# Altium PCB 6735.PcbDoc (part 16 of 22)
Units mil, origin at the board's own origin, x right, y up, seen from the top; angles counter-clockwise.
Board outline 2641.73 x 5165.35 mil, 6 copper layers (Top, Inner Layer 2, Inner Layer 3, Inner Layer 4, Inner Layer 5, Bottom), stack 35.7 mil thick; 1011 components, 790 nets, 4118 pads, 9325 vias.
Unrouted connection lines stored in the file: 4610.
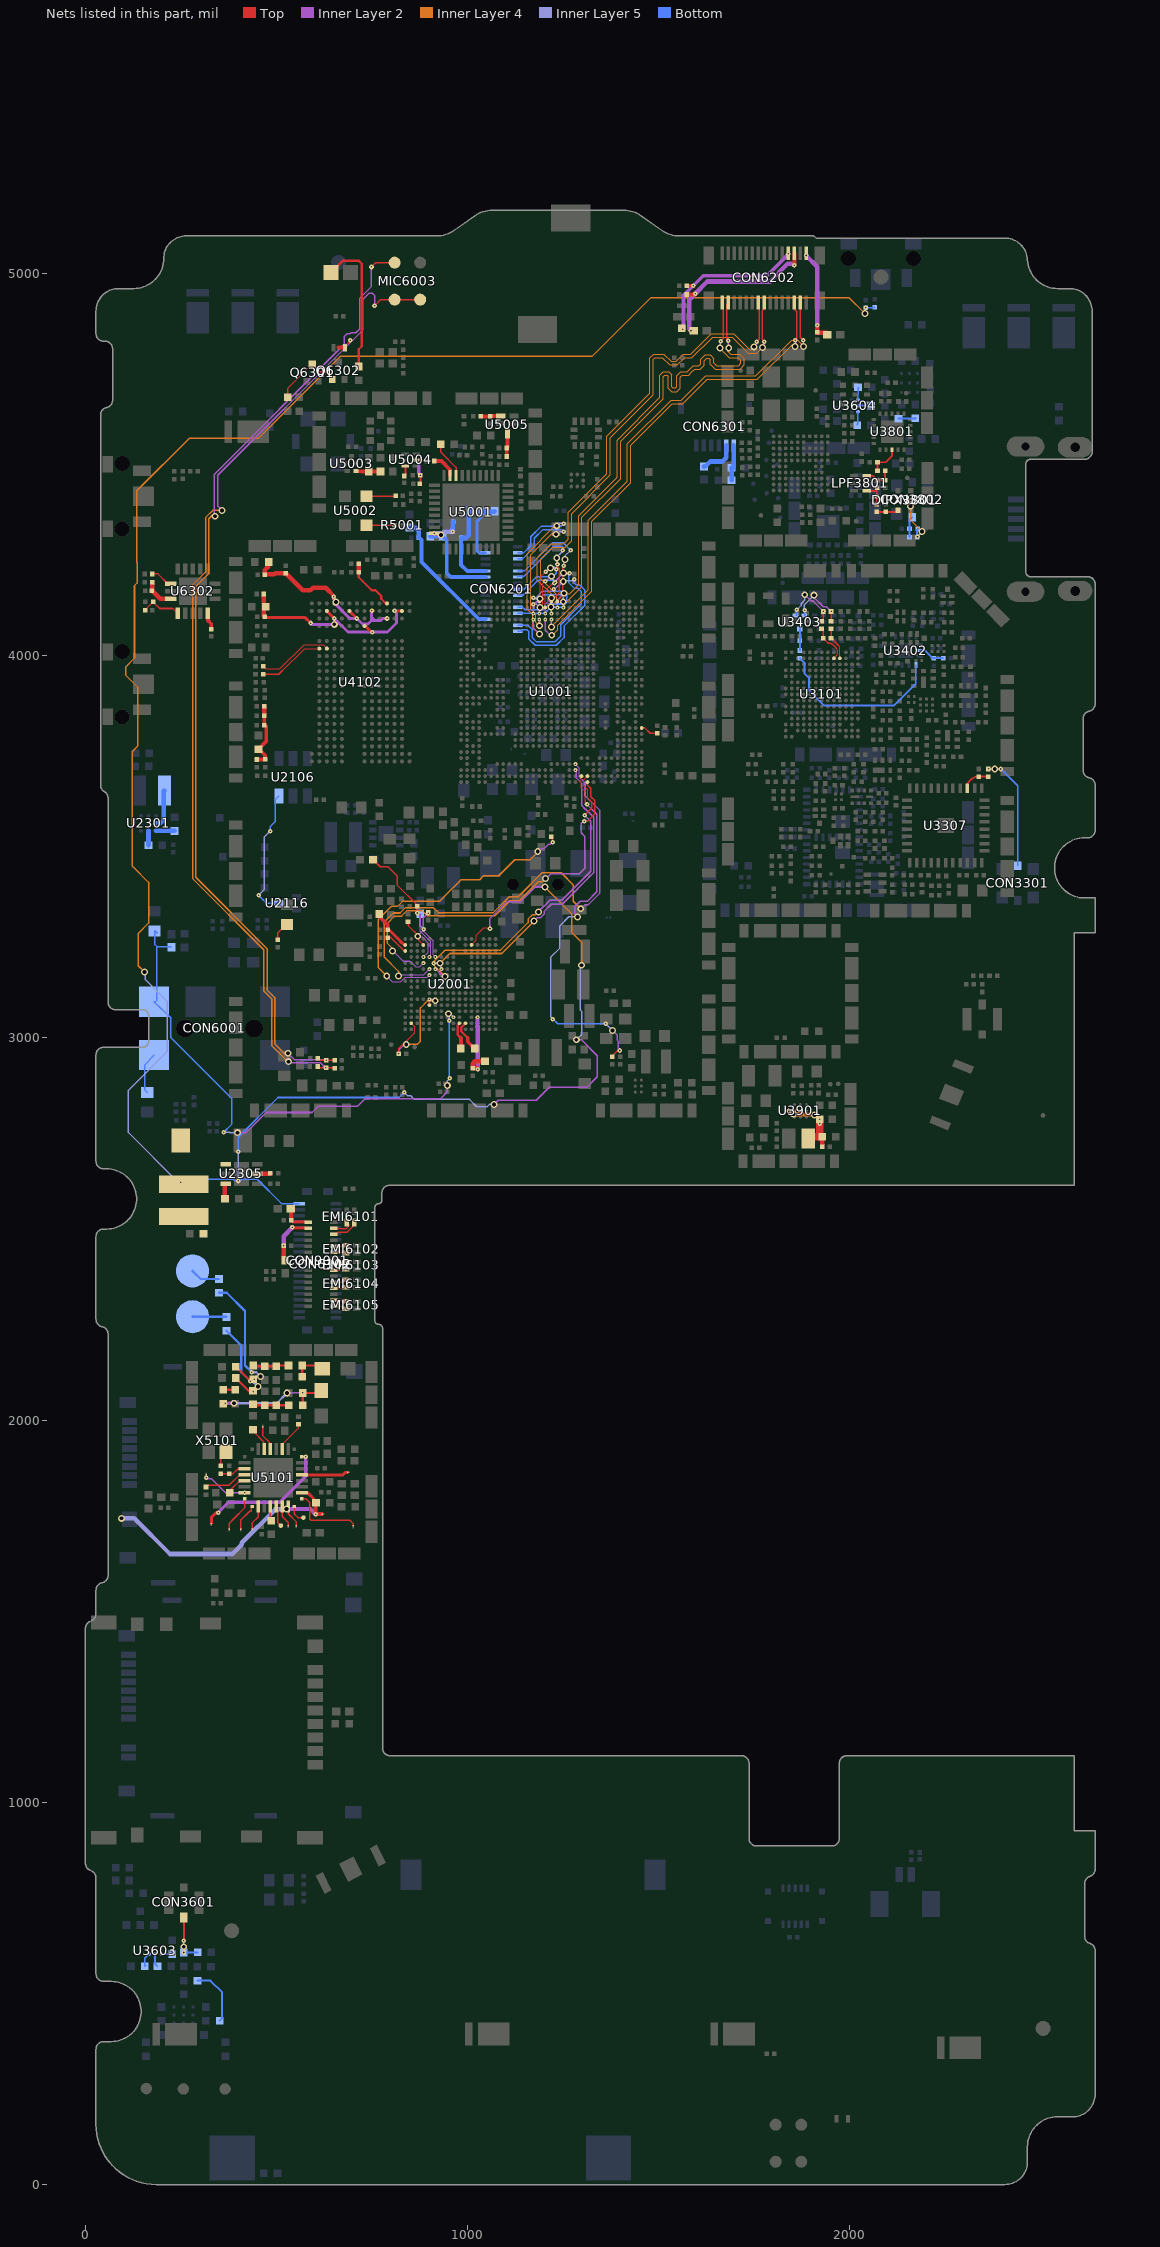
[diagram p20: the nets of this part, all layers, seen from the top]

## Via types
v1: diameter 12, hole 4, Top to Inner Layer 2, 3329 vias
v2: diameter 12, hole 4, Inner Layer 5 to Bottom, 3071 vias
v3: diameter 18, hole 10, Inner Layer 2 to Inner Layer 5, 1928 vias
v4: diameter 10, hole 4, Top to Inner Layer 2, 525 vias
v5: diameter 20, hole 12, Top to Bottom, 472 vias

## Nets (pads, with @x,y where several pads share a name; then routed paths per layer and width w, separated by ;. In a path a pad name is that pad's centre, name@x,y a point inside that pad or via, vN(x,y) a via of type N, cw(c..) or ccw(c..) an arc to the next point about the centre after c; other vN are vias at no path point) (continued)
N21349567: D6301.1 R6350.2 | length 367.8
  Top w6: D6301.1@642.78,5002.92 672.82,5032.96 715.61,5032.96 722.95,5025.62 722.95,4809.85 714.88,4801.77 R6350.2@714.88,4756.78
N21349614: Q6301.3 Q6302.1 R6352.2 | length 183.6
  Top w4: R6352.2@528.95,4675.99 528.95,4699.11 592.97,4763.13 Q6301.3@593.95,4763.13 594.94,4763.13 615.07,4742.99 626.55,4742.99 645.7,4723.84 Q6302.1@645.7,4722.85
N22234659: C6203.1 CON6201.29 R6201.1 | length 169.8
  Bottom w8: C6203.1@1038.72,4377.31 1034.95,4377.31 1034.95,4361.49 1023.95,4350.49 1023.95,4274.77 1029.83,4268.89 CON6201.29@1046.63,4268.89
  Bottom w12: C6203.1@1038.72,4377.31 1038.72,4377.09 1071.31,4377.09 R6201.1@1071.31,4378.09
N22234883: C6202.1 CON6201.18 R6204.1 | length 341.9
  Bottom w10: C6202.1@872.31,4309.09 878.95,4302.45 878.95,4245.54 1028.83,4095.66 CON6201.18@1046.63,4095.66
  Bottom w12: R6204.1@847.95,4335.49 847.95,4334.49 863.95,4334.49 872.31,4326.12 C6202.1@872.31,4309.09
N22234972: C6210.1 CON6202.6 R6209.1 | length 462.4
  Top w4: v1(1584.3,4850.09) R6209.1@1591.31,4850.09
  Top w10: C6210.1@1573.31,4945.09 1573.31,4945.42 1595.31,4945.42 v1(1595.31,4947.09) ; v1(1854.31,5022.09) 1854.69,5022.09 CON6202.6@1854.69,5053.06
  Inner Layer 2 w12: v1(1584.3,4850.09) 1579.31,4855.08 1579.31,4931.09 v1(1595.31,4947.09) 1627.31,4979.09 1790.92,4979.09 1836.92,5025.09 1854.31,5025.09 v1(1854.31,5022.09)
N22234982: C6207.1 CON6202.8 R6207.1 | length 431.4
  Top w4: R6207.1@1560.31,4857.09 v1(1563.31,4854.09)
  Top w8: C6207.1@1573.31,4968.09 1573.31,4968.16 1587.24,4968.16 1588.81,4966.59 v1(1590.31,4968.09)
  Inner Layer 2 w10: v1(1563.31,4854.09) 1564.31,4855.09 1564.31,4942.09 v1(1590.31,4968.09) 1616.31,4994.09 1783.06,4994.09 1830.78,5041.81 1830.78,5042.9 v1(1838.94,5051.05)
N22234984: C6206.1 CON6202.2 R6205.1 | length 246
  Top w12: v1(1914.31,4865.09) C6206.1@1914.31,4846.09 1914.31,4845.09 1940.31,4845.09 1940.31,4840.09 R6205.1@1941.31,4840.09
  Inner Layer 2 w12: v1(1885.31,5047.09) 1914.31,5018.09 v1(1914.31,4865.09)
N22235094: C6204.2 CON6201.25 R6203.1 | length 239.2
  Bottom w10: C6204.2@934.95,4311.99 945.31,4301.62 945.31,4216.12 955.54,4205.9 CON6201.25@1046.63,4205.9
  Bottom w12: R6203.1@902.45,4312.99 902.45,4311.99 C6204.2@934.95,4311.99
N22235098: C6201.1 CON6201.26 R6202.1 | length 230.3
  Bottom w10: C6201.1@982.95,4307.99 982.95,4237.49 998.79,4221.64 CON6201.26@1046.63,4221.64
  Bottom w12: C6201.1@982.95,4307.99 994.95,4307.99 1002.45,4315.49 1002.45,4374.99 R6202.1@1006.45,4378.99 ; R6202.1@1006.45,4379.99 R6202.1@1006.45,4378.99 ; R6202.1@1007.24,4378.99 R6202.1@1006.45,4378.99
N22266286: CON6102.28 EMI6101.3 | length 71.7
  Top w4: CON6102.28@649.55,2486.73 651.91,2489.09 658.31,2489.09 661.31,2492.09 684.78,2492.09 704.81,2512.12 704.81,2517.07 EMI6101.3@703.8,2517.07
N22266288: CON6102.29 EMI6101.2 | length 54.4
  Top w4: CON6102.29@649.55,2502.48 651.94,2500.09 681.31,2500.09 688.31,2507.09 688.31,2512.86 EMI6101.2@684.11,2517.07
N22266347: CON6102.22 EMI6103.3 | length 33.6
  Top w4: CON6102.22@649.55,2392.24 662.45,2392.24 665.81,2395.59 667.31,2397.09 676.62,2397.09 678.09,2395.62 EMI6103.3@680.54,2395.25
N22266349: CON6102.23 EMI6103.2 | length 38.1
  Top w4: CON6102.23@649.55,2407.99 665.63,2407.99 675.59,2417.94 680.54,2417.94 EMI6103.2@680.54,2414.93
N22266395: CON6102.19 EMI6104.3 | length 33.3
  Top w4: CON6102.19@649.55,2345 680.54,2344.99 EMI6104.3@680.54,2347.25
N22266397: CON6102.20 EMI6104.2 | length 33.6
  Top w4: CON6102.20@649.55,2360.75 674.35,2360.74 EMI6104.2@680.54,2366.93
N22266410: CON6102.25 EMI6102.3 | length 31.9
  Top w4: CON6102.25@649.55,2439.49 678.3,2439.48 EMI6102.3@680.54,2437.25
N22266412: CON6102.26 EMI6102.2 | length 31.7
  Top w4: CON6102.26@649.55,2455.23 678.84,2455.23 EMI6102.2@680.54,2456.93
N22266425: CON6102.16 EMI6105.3 | length 37.9
  Top w4: CON6102.16@649.55,2297.75 671.03,2297.75 680.54,2288.25 EMI6105.3@680.54,2291.25
N22266427: CON6102.17 EMI6105.2 | length 36.3
  Top w4: CON6102.17@649.55,2313.5 674.97,2313.5 679.04,2309.43 680.54,2307.93 EMI6105.2@680.54,2310.93
N33629520: C4111.1 C4112.1 R4101.1 U4102.B3 U4102.B12 U4102.B13 U4102.C4 U4102.D8 | length 571.9
  Top w4: C4111.1@466.95,4132.82 471.31,4132.82 C4111.1@471.31,4128.09
  Top w8: C4112.1@468.95,4101.49 470.95,4099.49 574.95,4099.49 v1(588.95,4085.49) ; U4102.B3@631.5,4117.12 v1(651.18,4097.43) ; U4102.D8@729.93,4077.75 730.98,4078.8 748.98,4060.8 v1(750.03,4061.85) ; v1(808.66,4117.11) U4102.B13@828.35,4117.12
  Top w12: C4111.1@466.95,4132.82 466.95,4103.49 C4112.1@468.95,4101.49 ; C4111.1@466.95,4133.49 R4101.1@466.95,4161.49
  Inner Layer 2 w8: v1(588.95,4085.49) 592.33,4082.11 v3(651.08,4082.11) 651.08,4097.33 v1(651.18,4097.43) 686.76,4061.85 v1(750.03,4061.85) 790.32,4061.85 813.95,4085.49 813.95,4111.83 v1(808.66,4117.11)
N33629528: C4113.1 C4114.1 R4102.1 U4102.A4 U4102.B6 U4102.B9 U4102.C7 U4102.C11 | length 521.7
  Top w8: v1(649.08,4154.11) 651.18,4152.11 U4102.A4@651.19,4136.8 ; U4102.B6@690.56,4117.12 v1(710.24,4097.43)
  Top w10: 638.95,4167.44 650.68,4155.71 v1(649.08,4154.11)
  Top w12: R4102.1@469.31,4212.09 R4102.1@469.31,4213.25 ; C4113.1@479.31,4245.09 478.31,4245.09 478.31,4233.11 469.31,4224.11 R4102.1@469.31,4213.25 ; 638.95,4167.44 628.9,4177.49 615.9,4177.49 615.56,4177.83 595.62,4177.83 588.62,4170.83 568.61,4170.83 C4114.1@523.95,4215.49 496.63,4215.49 494.39,4213.25 R4102.1@469.31,4213.25
  Inner Layer 2 w8: v1(649.08,4154.11) 649.08,4147.11 655.08,4141.11 v3(655.08,4140.11) 655.08,4135.11 654.58,4134.61 691.76,4097.43 v1(710.24,4097.43) 724.95,4082.72 739.17,4082.72 748.3,4091.85 748.3,4092.18 ; v1(749.61,4117.11) 748.3,4115.81 748.3,4101.24 ; v1(788.98,4097.43) 788.08,4097.64 778.73,4097.64 773.27,4092.18 757.37,4092.18 ; 748.3,4092.18 757.37,4092.18 ; 748.3,4092.18 748.3,4101.24 ; 748.3,4101.24 757.37,4092.18
N33630206: C4109.1 C4110.1 U4102.A11 | length 143.1
  Top w4: U4102.A11@788.98,4136.8 788.98,4137.46 U4102.A11@788.98,4136.8
  Top w6: C4110.1@714.95,4218.49 714.95,4205.45 749.31,4171.09 758.86,4171.09 773.8,4156.15 773.8,4148.91 785.9,4136.8 U4102.A11@788.98,4136.8
  Top w12: C4110.1@714.95,4218.49 C4109.1@714.95,4240.49
N33630402: R4103.2 U4102.G2 | length 174.7
  Top w3: 514.95,3960.49 573.15,4018.69 U4102.G2@611.82,4018.69
  Top w4: R4103.2@464.95,3951.49 505.95,3951.49 514.95,3960.49
N33630406: R4104.2 U4102.G3 | length 199.7
  Top w3: R4104.2@464.95,3972.49 471.95,3965.49 508.95,3965.49 572.02,4028.56 621.63,4028.56 U4102.G3@631.5,4018.69
N35189465: L5002.2 U5001.38 | length 98.7
  Top w4: L5002.2@929.31,4553.09 929.31,4532.8 969.71,4492.4 U5001.38@969.71,4471.17
N35189467: R5015.1 U5004.6 | length 27.6
  Top w4: R5015.1@834.08,4470.11 834.08,4471.11 837.3,4474.33 U5004.6@837.3,4496.36
N35189484: L5007.1 R5014.2 U5005.4 | length 53.3
  Top w10: R5014.2@1034.31,4626.09 L5007.1@1059.08,4626.11 1059.08,4626.8 U5005.4@1086.86,4626.8
N35189556: C5013.1 C5014.1 U5001.9 | length 90.4
  Inner Layer 2 w12: v1(913.02,4319.99) 913.02,4319.09 930.31,4319.09 v3(930.31,4316.09)
  Inner Layer 5 w12: v3(930.31,4316.09) 930.24,4316.16 938.06,4323.99 v2(961.43,4323.99)
  Bottom w4: v2(961.43,4323.99) 961.42,4327.97 959.45,4330.99 961.45,4328.99 961.95,4328.49 C5013.1@961.45,4328.49
  Bottom w12: C5013.1@961.45,4327.99 961.45,4328.49 961.45,4328.99 961.45,4350.49 C5014.1@961.95,4350.49
N35189587: R5007.2 U5001.39 | length 66
  Top w10: R5007.2@912.95,4509.49 931.13,4509.49 953.96,4486.66 U5001.39@953.96,4471.17
N35190528: R5003.1 U5002.4 | length 77.1
  Top w4: U5002.4@735.43,4417.1 786.02,4417.1 ; 786.03,4417.11 809.57,4417.11 810.95,4418.49 R5003.1@811.95,4418.49
N35190536: R5001.1 U5002.3 | length 73.7
  Top w4: U5002.3@735.43,4341.12 791.13,4341.11 R5001.1@809.08,4341.11
N35190564: C5012.2 R5008.1 U5004.2 | length 67.6
  Top w5: U5004.2@864.86,4512.11 865.08,4511.89 v1(865.08,4511.11) ; R5008.1@875.08,4450.11 876.08,4450.11 v1(876.08,4472.11)
  Inner Layer 2 w8: v1(865.08,4511.11) 871.95,4504.24 871.95,4476.24 v1(876.08,4472.11)
N35190588: C5011.1 L5003.1 U5003.4 | length 64.9
  Top w10: U5003.4@707.4,4482.74 722.3,4482.74 722.93,4482.11 C5011.1@741.08,4482.11 L5003.1@772.08,4482.11
N35190689: C5016.1 L5006.1 U5005.1 | length 60.6
  Top w10: C5016.1@1102.08,4521.11 1102.08,4543.49 L5006.1@1101.95,4543.49 1104.08,4545.62 U5005.1@1104.08,4580.69
N42705003: C5102.1 R5102.2 R5104.1 | length 368.7
  Top w4: R5104.1@439.31,2107.09 440.31,2106.09 v1(441.31,2107.09)
  Top w6: C5102.1@393.31,2140.09 426.31,2107.09 R5104.1@439.31,2107.09 v1(441.31,2107.09)
  Inner Layer 2 w4: v1(441.31,2107.09) 440.43,2107.97 446.95,2114.49 v3(457.95,2114.49)
  Inner Layer 5 w6: v2(434.95,2125.49) 446.95,2125.49 v3(457.95,2114.49)
  Bottom w6: R5102.2@349.31,2333.09 369.95,2333.09 417.31,2285.72 417.31,2143.12 v2(434.95,2125.49)
N42705119: C5117.2 U5101.22 | length 64.3
  Top w4: C5117.2@438.31,1975.09 438.31,1971.31 465.95,1943.67 465.95,1923.99 U5101.22@467.68,1923.99
N42705839: C5110.1 R5105.2 | length 32
  Top w6: C5110.1@360.31,2079.09 R5105.2@392.31,2079.09
N42705853: C5105.2 C5107.2 C5109.1 R5104.2 | length 96
  Top w6: R5104.2@439.31,2143.09 439.31,2141.09 C5105.2@469.31,2141.09 C5107.2@499.31,2141.09 499.31,2143.09 C5109.1@531.31,2143.09
N42705857: C5108.2 C5110.2 C5111.1 L5101.2 | length 319.4
  Top w4: C5110.2@359.32,2043.09 C5110.2@360.31,2043.09 ; C5110.2@359.31,2044.09 C5110.2@360.31,2043.09 ; v1(365.31,2044.09) 361.31,2044.09 C5110.2@360.31,2043.09
  Top w6: C5108.2@568.1,2039.09 C5108.2@568.31,2039.09 v1(568.31,2071.09) ; C5111.1@569.31,2072.09 v1(568.31,2071.09) ; L5101.2@608.81,2086.09 L5101.2@617.31,2077.59 610.81,2071.09 v1(568.31,2071.09)
  Inner Layer 2 w4: v3(527.31,2071.09) v1(568.31,2071.09)
  Inner Layer 2 w9: v1(365.31,2044.09) 384.31,2044.09 v3(388.82,2044.08)
  Inner Layer 5 w6: v3(388.82,2044.08) 500.31,2044.09 v3(527.31,2071.09)
N42705859: R5108.1 R5130.2 U5101.27 | length 67.3
  Top w4: R5108.1@354.31,1860.09 R5130.2@376.31,1860.09 386.13,1860.09 398.75,1872.71 U5101.27@416.4,1872.71
N42705927: C5104.1 C5106.1 C5108.1 R5103.2 | length 96
  Top w6: R5103.2@438.31,2041.09 438.31,2039.09 C5106.1@469.31,2039.09 C5104.1@499.31,2039.09 C5108.1@532.31,2039.09
N42705929: R5116.2 U5101.4 | length 40
  Top w4: U5101.4@483.43,1774.19 483.43,1737.09 R5116.2@486.3,1737.09
N42705933: C5101.1 R5101.2 R5103.1 | length 269.1
  Top w4: R5103.1@438.31,2077.09 439.31,2077.09 v1(439.31,2074.09)
  Top w6: C5101.1@393.31,2110.09 428.31,2075.09 438.31,2075.09 R5103.1@438.31,2077.09
  Inner Layer 2 w4: v1(439.31,2074.09) 438.92,2074.48 451.86,2087.43 v3(451.46,2087.83)
  Inner Layer 5 w6: v2(430.95,2101.49) 437.31,2101.49 440.68,2098.09 441.2,2098.09 v3(451.46,2087.83)
  Bottom w6: R5101.2@368.95,2233.83 407.31,2195.47 407.31,2125.12 v2(430.95,2101.49)
N42705947: C5109.2 C5112.2 L5102.2 | length 87.8
  Top w6: C5112.2@567.31,2113.09 C5109.2@567.31,2143.09 613.52,2143.09 619.81,2136.8 L5102.2@619.81,2134.09
N42705966: C5116.2 U5101.19 | length 83.7
  Top w4: U5101.19@514.92,1923.99 514.21,1923.99 514.21,1936.02 557.31,1979.13 C5116.2@557.31,1989.09
N42706036: C5119.2 U5101.29 | length 57.4
  Top w4: C5119.2@377.31,1810.09 377.31,1810.67 376.73,1810.67 381.31,1815.26 381.31,1819.49 404.06,1842.23 416.4,1842.23 U5101.29@416.4,1841.22
N42706071: C5120.2 U5101.28 | length 115.5
  Top w4: C5120.2@315.31,1825.09 320.31,1830.09 376.46,1830.09 404.21,1857.83 416.4,1857.83 U5101.28@416.4,1856.96
N42706085: R5108.2 X5101.1 | length 43.1
  Top w4: R5108.2@354.31,1880.09 354.31,1903.91 X5101.1@367.95,1917.55
N42706217: ANT5101.1 R5101.1 | length 90.9
  Bottom w6: ANT5101.1@281.08,2271.49 ANT5101.1@280.08,2270.49 368.95,2270.49 R5101.1@368.95,2269.83
N42706219: ANT5102.1 R5102.1 | length 78.1
  Bottom w6: ANT5102.1@280.08,2390.49 301.48,2369.09 R5102.1@349.31,2369.09
N42706237: TP5101.1 U5101.8 | length 47.5
  Top w4: U5101.8@546.42,1774.19 546.42,1754.42 555.75,1745.09 TP5101.1@570.31,1745.09
N42706293: TP5102.1 U5101.5 | length 55.1
  Top w4: U5101.5@499.18,1774.19 502.95,1770.41 502.95,1732.44 TP5102.1@511.3,1724.09
N45548966: C6034.2 C6035.1 MIC6003.4 R6025.1 | length 2598.1
  Top w4: C6035.1@607.68,2946.69 612.28,2942.09 C6034.2@630.31,2942.09 ; v1(630.31,2941.09) C6034.2@630.31,2942.09 ; R6025.1@652.31,2942.09 C6034.2@630.31,2942.09 ; v1(748.31,5017.09) 759.74,5028.52 MIC6003.4@808.85,5028.52
  Inner Layer 2 w4: v3(338.95,4364.83) 336.94,4366.84 336.94,4474.3 677.31,4814.67 677.31,4835.09 684.31,4842.09 692.31,4842.09 694.89,4844.67 707.31,4844.67 717.95,4855.31 717.95,4935.72 748.31,4966.09 v1(748.31,5017.09) ; v3(529.95,2959.83) 530.17,2960.05 547.13,2943.09 628.31,2943.09 v1(630.31,2941.09)
  Inner Layer 4 w4: v3(338.95,4364.83) 334.69,4369.09 333.31,4369.09 322.31,4358.09 322.31,4215.25 288.31,4181.25 288.31,3420.17 475.31,3233.17 475.31,3125.41 495.31,3105.41 495.31,2984.03 519.51,2959.83 v3(529.95,2959.83)
N45548968: C6034.1 C6039.1 MIC6003.2 MIC6003.3 R6026.1 SH6004.1 | length 2702
  Top w4: C6039.1@607.31,2925.09 610.31,2925.09 613.31,2922.09 v1(628.31,2922.09) C6034.1@630.31,2922.09 642.31,2922.09 ; R6026.1@652.31,2921.09 R6026.1@651.31,2921.09 ; SH6004.1@679.31,4806.09 679.31,4810.09 693.31,4824.09 695.31,4824.09 v1(693.18,4825.73) ; v1(756.3,4915.09) 772.88,4931.66 MIC6003.3@808.85,4931.66 MIC6003.2@875.78,4931.66 ; 642.31,2922.09 650.31,2922.09 R6026.1@651.31,2921.09 ; 642.31,2922.09 643.31,2921.09 R6026.1@651.31,2921.09
  Inner Layer 2 w4: v3(357.31,4380.09) 345.87,4391.53 345.87,4471.9 693.18,4819.21 ; v3(530.95,2937.83) 530.95,2936.09 535.31,2936.09 536.31,2935.09 614.63,2935.09 627.63,2922.09 v1(628.31,2922.09) ; v1(756.3,4915.09) 756.3,4942.48 750.42,4948.36 741.9,4948.36 725.95,4932.41 725.95,4851.98 v1@697.06,4823.09 ; 693.18,4819.21 v1(693.18,4825.73) 695.31,4824.09 695.69,4824.47 v1@697.06,4823.09 ; 693.18,4819.21 v1@697.06,4823.09
  Inner Layer 4 w4: v3(357.31,4380.09) 333,4380.09 314.31,4361.4 314.31,4218.91 280.31,4184.91 280.31,3416.77 466.31,3230.77 466.31,3123.09 487.31,3102.09 487.31,2980.43 530.43,2937.31 v3(530.95,2937.83)
N46126307: C1101.2 C1102.1 C1103.1 R1103.2 R1105.2 R1106.1 | length 183
  Top w3: C1102.1@467.81,3818.33 C1102.1@467.81,3820.33 ; R1106.1@467.81,3837.33 R1106.1@467.81,3843.33
  Top w10: C1101.2@447.81,3728.33 447.81,3728.54 R1105.2@470.13,3728.54 470.13,3739.54 C1103.1@453.57,3756.09 ; R1106.1@467.81,3837.33 467.81,3820.33 472.81,3815.33 472.81,3775.33 C1103.1@453.57,3756.09 ; C1103.1@453.57,3756.09 453.57,3755.33 C1103.1@452.81,3755.33 C1103.1@453.57,3756.09
  Top w12: R1106.1@467.81,3843.33 467.81,3855.35 467.95,3855.49 R1103.2@467.95,3867.49
N46488991: R2003.2 U2001.N2 | length 76.9
  Top w4: R2003.2@843.95,3303.49 843.95,3294.41 872.31,3266.04 872.31,3254.96 U2001.N2@884.09,3243.19
N46497626: C2008.1 R2026.2 | length 51
  Top w4: R2026.2@503.31,3257.09 503.31,3274.66 525.56,3296.91 C2008.1@527.56,3296.91
N46513471: C2038.1 U2001.G15 | length 75.8
  Top w4: C2038.1@982.31,2972.15 C2038.1@986.31,2972.15
  Top w6: U2001.G15@978.57,3038.47 973.85,3033.74 973.85,3008.55 979.25,3003.15
  Top w10: 979.25,3003.15 982.31,3000.09 C2038.1@982.31,2972.15
N46513473: C2038.2 U2001.F15 | length 85.6
  Top w6: U2001.F15@994.32,3038.47 983.26,3027.41 983.26,3016.81 990.31,3009.76 990.64,3009.76 1000.31,3000.09
  Top w10: 1000.31,3000.09 1000.31,2990.15 C2038.2@1018.31,2972.15
N46513502: C2022.1 R2048.1 U2001.D14 | length 209.5
  Top w4: v1(1026.48,2918.32) 1029.31,2918.09 1030.31,2919.09 v1(1026.48,2918.32)
  Top w12: v1@1026.65,2918.48 v1(1026.48,2918.32) 1026.48,2920.65 C2022.1@1013.31,2920.65 1013.31,2933.15 1018.98,2938.81 1040.75,2938.81 1042.56,2937.01 1044.31,2937.01 1044.31,2938.76 R2048.1@1045.31,2938.76
  Inner Layer 2 w10: 1025.82,3029.83 v4(1025.82,3054.22)
  Inner Layer 2 w12: 1025.82,3029.83 1026.07,3029.58 1026.07,3015.11 1025.95,3014.99 1025.95,2918.85 v1(1026.48,2918.32)
N46536440: R2044.2 U2001.N4 | length 160.9
  Inner Layer 2 w3: v3@872.02,3269.3 869.72,3267 v3(869.31,3266.09) 871.31,3264.09 880.82,3264.09 896.8,3248.1 896.8,3224.41 v4(884.09,3211.7)
  Inner Layer 5 w4: v3(869.31,3266.09) 868.81,3266.59 885.81,3283.59 v2(885.31,3284.09)
  Bottom w4: R2044.2@875.95,3324.49 R2044.2@875.95,3323.49 ; v2(885.31,3284.09) 875.95,3293.45 R2044.2@875.95,3321.15 ; R2044.2@875.95,3321.15 R2044.2@876.82,3322.61 ; R2044.2@875.95,3321.15 875.31,3320.09 875.31,3323.49 R2044.2@875.95,3323.49 ; R2044.2@875.95,3321.15 R2044.2@875.95,3323.49 ; R2044.2@875.95,3323.49 R2044.2@876.82,3322.61 ; R2044.2@875.95,3323.49 876.29,3323.49 R2044.2@876.95,3322.83 ; R2044.2@876.82,3322.61 R2044.2@876.95,3322.83 ; R2044.2@876.82,3322.61 876.95,3322.49 R2044.2@876.95,3322.83
N46536454: C2051.1 R2045.2 U2001.M4 | length 332.4
  Top w4: R2045.2@752.31,3466.09 753.31,3466.09 771.31,3448.09 791.31,3448.09 816.31,3423.09 816.31,3399.04 867.95,3347.4 C2051.1@867.95,3344.49 868.31,3344.49 868.31,3327.09 v1(867.95,3326.83)
  Inner Layer 2 w3: 875.31,3290.5 875.31,3279.68 902.8,3252.19 902.8,3214.66 v4(899.83,3211.7)
  Inner Layer 2 w4: v1(867.95,3326.83) 868.31,3327.09 868.81,3327.59 875.31,3321.09 875.31,3290.5
N46631817: C2030.1 U2001.L4 | length 139.2
  Top w4: v1(896.31,3326.09) 896.31,3328.49 C2030.1@896.95,3328.49
  Inner Layer 2 w3: 883.31,3293.85 883.31,3280.58 909.31,3254.58 909.31,3217.97 915.58,3212.09 v4(915.58,3211.7)
  Inner Layer 2 w4: 883.31,3293.85 883.31,3313.09 v1(896.31,3326.09) 896.31,3327.19 v1@897.61,3328.49
N46632525: C2057.1 U2001.T3 | length 61.2
  Top w4: C2057.1@790.95,3262.49 791.95,3263.49 797.95,3263.49 831.95,3229.49 834.8,3229.49 U2001.T3@836.84,3227.44
N46647149: C2031.1 R2042.2 U2001.T2 | length 122.9
  Top w8: C2031.1@790.95,3283.49 793.91,3283.49 823.92,3253.48 823.92,3252.95 835.26,3241.61 U2001.T2@836.84,3243.19 ; U2001.T2@836.84,3243.19 834.24,3243.19 U2001.T2@836.84,3243.19
  Top w10: R2042.2@768.31,3324.09 768.31,3323.09 765.85,3323.09 765.85,3320.62 790.95,3295.52 C2031.1@790.95,3283.49
N46925420: U2106.3 U2116.3 | length 341.9
  Inner Layer 5 w4: v2(452.95,3373.49) 467.38,3387.92 467.38,3525.16 v2(483.31,3541.09)
  Bottom w4: v2(452.95,3373.49) 474.35,3352.09 U2116.3@504.69,3352.09 ; v2(483.31,3541.09) 483.31,3553.1 495.95,3565.74 495.95,3622.91 U2106.3@505.91,3632.88
N46931772: R2002.2 U2001.M7 | length 843.2
  Top w4: R2002.2@1218.95,3526.49 1221.67,3526.49 1221.67,3512.24 v1(1223.03,3512.24)
  Inner Layer 2 w3: v3(788.31,3162.09) 803.31,3147.09 824.31,3147.09 836.57,3159.35 894.73,3159.35 v4(899.83,3164.45)
  Inner Layer 2 w4: v3(1183.31,3488.09) 1190.31,3495.09 1200.02,3495.09 1212.02,3507.09 1216.86,3507.09 1222.52,3512.75 v1(1223.03,3512.24)
  Inner Layer 4 w4: v3(788.31,3162.09) 765.95,3184.45 765.95,3309.98 800.06,3344.09 816.25,3344.09 829.25,3357.09 925.66,3357.09 982.66,3414.09 1031.4,3414.09 1041.4,3424.09 1081.23,3424.09 1123.23,3466.09 1162.87,3466.09 1184.09,3487.31 v3(1183.31,3488.09)
N46931792: C2023.2 U2001.M12 U2001.R15 | length 344.4
  Top w3: U2001.R15@852.59,3038.47 862.01,3029.05 862.01,3014.29 860.81,3013.09
  Top w4: C2023.2@819.31,2958.09 v1(819.31,2959.09) 819.31,2971.59 860.81,3013.09 ; U2001.M12@899.83,3085.71 899.83,3099.71 900.45,3100.33 v4(899.95,3100.83)
  Inner Layer 2 w4: v1(819.31,2959.09) 819.31,2967.44 834.96,2983.09 v3(839.32,2983.09) ; v4(899.95,3100.83) 909.57,3100.83 913.31,3097.09 914.31,3098.09 v3(915.31,3097.09)
  Inner Layer 4 w4: v3(839.32,2983.09) 868.31,2983.09 876.31,2991.09 876.31,3078.3 895.1,3097.09 v3(915.31,3097.09)
N47019425: L3610.2 U3603.1 | length 40.9
  Bottom w4: L3610.2@158.19,573.96 L3610.2@155.31,571.09 155.31,591.96 U3603.1@166.56,603.22
N47019540: R3608.2 R3609.1 | length 154.2
  Bottom w5: R3609.1@292.95,533.49 326.9,533.49 357.3,503.09 357.3,434.84 R3608.2@350.95,428.49
N47019602: C3601.2 CON3601.2 R3603.1 | length 129.1
  Top w5: v1(257.31,637.33) CON3601.2@257.31,698.7
  Inner Layer 2 w3: v3(257.31,622.11) v1(257.31,637.33)
  Inner Layer 5 w3: v2(257.31,607.09) v3(257.31,622.11)
  Bottom w5: R3603.1@257.31,608.09 v2(257.31,607.09) 292.93,607.09 C3601.2@293.53,607.69
N47514918: D2301.1 PL2303.2 U2305.4
N47514920: C2312.1 PL2303.1 R2308.2 U2305.6 | length 41.1
  Top w12: C2312.1@364.95,2579.49 364.95,2618.9 U2305.6@366.61,2618.9
N47514951: C2315.1 U2305.2 | length 35.7
  Top w12: U2305.2@449.29,2644.49 483.95,2644.49 C2315.1@483.95,2645.49
N48048238: L3609.2 U3603.6 | length 34.6
  Bottom w5: U3603.6@182.31,603.22 182.31,577.09 L3609.2@188.31,571.09
N48113596: C3603.1 U3603.5 | length 29.3
  Bottom w5: U3603.5@198.06,603.22 210.09,603.21 210.21,603.09 C3603.1@227.31,603.09
N48144087: L3611.2 U3604.6 | length 34.1
  Bottom w5: U3604.6@2021.18,4654.09 L3611.2@2055.3,4654.09
N48144113: C3604.1 U3604.5 | length 32.3
  Bottom w4: U3604.5@2021.18,4669.84 2021.17,4682.96 2021.3,4683.09 C3604.1@2021.3,4702.09
N48144163: L3612.2 U3604.1 | length 36
  Bottom w4: L3612.2@2019.31,4603.09 2019.31,4606.09 2021.17,4607.95 U3604.1@2021.18,4638.34
N48144216: R3611.2 R3612.1 | length 46
  Bottom w5: R3612.1@2127.3,4620.09 2171.3,4620.09 R3611.2@2171.3,4621.09 R3611.2@2171.3,4622.09
N48243655: R2320.1 U2301.B1 | length 37.3
  Bottom w12: R2320.1@164.95,3504.49 U2301.B1@164.95,3541.81
N48243675: PL2305.2 U2301.A2 | length 102.7
  Bottom w12: U2301.A2@184.64,3561.5 195.95,3561.5 204.55,3570.1 204.55,3647.09 PL2305.2@206.79,3647.09
N48243690: C2322.1 U2301.A1 | length 48.5
  Bottom w12: U2301.A1@184.64,3541.81 206.62,3541.82 206.95,3541.49 C2322.1@232.95,3541.49
N48322202: C6106.1 CON6102.2 R6104.1 | length 148.1
  Top w8: R6104.1@518.31,2423.09 522.31,2419.09 R6104.1@522.31,2418.09 ; v1(541.31,2504.09) 541.31,2502.47 CON6102.2@582.62,2502.48
  Top w12: v1(518.31,2456.09) 518.31,2423.09 518.31,2419.09 R6104.1@522.31,2419.09
  Inner Layer 2 w12: v1(518.31,2456.09) 518.31,2481.09 v1(541.31,2504.09)
N48322224: C6107.1 CON6102.1 R6105.1 | length 77.3
  Top w8: C6107.1@538.31,2523.09 543.18,2518.22 CON6102.1@582.62,2518.23
  Top w12: R6105.1@537.31,2553.09 538.31,2553.09 C6107.1@538.31,2523.09
N48523226: R6318.2 U6302.5 | length 45.5
  Top w10: U6302.5@320.32,4110.76 320.32,4092.23 328.95,4083.6 R6318.2@328.95,4068.83
N48523292: C6305.1 R6308.1 U6302.1 | length 108.8
  Top w4: R6308.1@156.95,4118.83 155.95,4118.83 155.95,4119.33 168.95,4132.33 ; 168.99,4132.33 176.95,4140.29 C6305.1@176.95,4140.83 194.31,4123.47 228.87,4123.47 U6302.1@241.58,4110.76
N48523353: C6304.1 R6307.1 U6302.16 | length 78.5
  Top w12: C6304.1@174.95,4191.83 174.95,4169.83 195.64,4149.14 U6302.16@222.88,4149.15
N48523359: C6306.1 U6302.14 | length 58.4
  Top w4: C6306.1@174.95,4213.83 189.92,4213.83 215.24,4188.52 U6302.14@222.88,4188.51
NFC_EINT: SH5112.2 U5101.7 | length 59.1
  Top w4: U5101.7@530.67,1774.19 530.67,1754.77 550.95,1734.49 SH5112.2@550.95,1723.49
NFC_I2C_SCL: SH5117.2 U5101.1 | length 74.6
  Top w4: SH5117.2@405.95,1714.49 405.95,1737.87 429.85,1761.77 433.85,1761.77 433.85,1771.85 U5101.1@436.18,1774.19
NFC_I2C_SDA: SH5118.2 U5101.2 | length 66.3
  Top w4: SH5118.2@435.95,1714.49 435.95,1730.49 451.93,1746.47 U5101.2@451.93,1774.19
NFC_IRQ: SH5113.2 U5101.6 | length 57.3
  Top w4: U5101.6@514.92,1774.19 514.92,1747.51 530.95,1731.49 SH5113.2@530.95,1723.49
NFC_OSC_EN: SH5116.2 U5101.32 | length 96.2
  Top w4: SH5116.2@375.95,1714.49 375.95,1729.68 389.31,1743.04 416.4,1770.14 U5101.32@416.4,1793.97
NFC_RST: SH5114.2 U5101.31 | length 126.4
  Top w4: v1(316.31,1849.09) SH5114.2@316.31,1857.09 ; U5101.31@416.4,1809.72 416.4,1810 v1(416.31,1810.09) U5101.31@416.77,1810.09 ; U5101.31@416.4,1809.72 416.54,1809.86 U5101.31@416.77,1810.09 ; U5101.31@416.4,1809.72 U5101.31@416.77,1810.09
  Inner Layer 2 w4: v1(316.31,1849.09) 320.31,1848.09 320.31,1847.09 329.31,1847.09 366.31,1810.09 v1(416.31,1810.09)
NFC_SWP1: SH5103.2 U5101.16 | length 368.9
  Top w4: U5101.16@566.2,1904.21 576.2,1904.2 v1(576.31,1904.09)
  Top w8: SH5103.2@329.31,1729.09 329.31,1745.09 342.31,1758.09 v1(347.31,1758.09)
  Inner Layer 2 w8: v1(347.31,1758.09) 374.31,1785.09 508.31,1785.09 576.31,1853.09 v1(576.31,1904.09)
NFC_SWP2: SH5106.2 U5101.13 | length 122.5
  Top w8: U5101.13@566.2,1856.96 673.74,1856.96 680.26,1863.49 SH5106.2@685.95,1863.49
NFC_SWPIO: SH5108.2 U5101.9 | length 193.2
  Top w4: U5101.9@566.2,1793.97 577.52,1793.97 586.95,1784.54 586.95,1740.44 589.78,1737.61 692.5,1737.61 700.31,1729.8 SH5108.2@700.31,1723.09
NFC_VCCSWP: C5122.1 SH5107.2 U5101.10 | length 702.8
  Top w8: U5101.10@566.2,1809.72 581.75,1809.72 603.3,1788.16 C5122.1@603.3,1784.09
  Top w10: C5122.1@603.3,1784.09 602,1784.09 v1(602,1753.44) 602.65,1754.09 SH5107.2@619.3,1754.09
  Inner Layer 2 w10: v3(526.31,1767.09) 588.35,1767.09 v1(602,1753.44)
  Inner Layer 5 w12: v3(94.31,1743.09) 127.78,1743.09 221.04,1649.83 384.36,1649.83 408.95,1674.42 408.95,1678.97 497.07,1767.09 v3(526.31,1767.09)
NFC_VENB: SH5115.2 U5101.21 | length 67.4
  Top w4: SH5115.2@463.31,1982.09 463.31,1960.04 481.95,1941.4 481.95,1938.18 484.13,1936.01 484.13,1923.99 U5101.21@483.43,1923.99
PA_VDD: C3914.1 C3915.1 PL3901.2 R3906.1 U3901.C2 | length 274.9
  Top w4: v1(1921.31,2775.56) 1921.31,2763.56 1927.31,2757.56 R3906.1@1927.31,2741.56
  Top w10: v1(1839.89,2808.67) 1839.89,2808.94 U3901.C2@1854.93,2808.94
  Top w12: C3915.1@1927.31,2715.56 1927.31,2725.99 1927.31,2734.35 R3906.1@1927.31,2741.56
  Top w20: PL3901.2@1890.51,2736.56 1890.51,2741.56 R3906.1@1927.31,2741.56 1924.1,2744.77 1921.08,2744.77 v1(1921.08,2787.58)
  Inner Layer 2 w12: v1(1839.89,2808.67) 1839.89,2807.7 1846.73,2800.86 v3(1852.86,2800.86) ; v3(1907.62,2798.21) 1911.83,2798.21 1921.08,2788.96 v1(1921.08,2787.58) 1921.2,2787.58 1921.2,2775.56 v1(1921.31,2775.56)
  Inner Layer 4 w12: v3(1852.86,2800.86) 1880.02,2800.86 1880.31,2800.56 1907.62,2800.56 v3(1907.62,2798.21)
POLE3_J: BEAD6001.2 CON6001.2 | length 109.9
  Bottom w4: BEAD6001.2@161.95,2857.08 155.31,2863.72 155.31,2928.83 CON6001.2@179.31,2954.83
POLE4_J: CON6001.1 L6001.1 L6002.2 U2001.H14 | length 1559.4
  Inner Layer 2 w4: v3(397.91,2752.09) 420.31,2752.09 473.05,2804.83 592.77,2804.83 609.03,2821.09 711.44,2821.09 731.44,2841.09 928.84,2841.09 946.77,2859.02 v3(946.77,2875.09) ; v3(949.65,3063.11) 954.11,3063.11 962.91,3054.31 v4(962.83,3054.22)
  Inner Layer 5 w4: v2(361.58,2753.01) 377.4,2753.01 378.31,2752.09 v3(397.91,2752.09) ; v3(946.77,2875.09) 946.77,2887.61 v2(953.25,2894.09) ; v3(949.65,3063.11) 950.93,3063.44 951.31,3063.44 v2(951.31,3045.09)
  Bottom w4: L6001.1@224.95,3237.49 224.95,3239.09 187.03,3239.09 ; v2(361.58,2753.01) 382.31,2773.74 382.31,2842.12 223.16,3001.27 223.16,3052.74 CON6001.1@179.31,3094.59 183.53,3094.59 187.03,3098.09 187.03,3239.09 ; v2(951.31,3045.09) 951.31,2896.03 v2(953.25,2894.09) ; L6002.2@180.95,3279.9 L6002.2@181.54,3279.9 ; L6002.2@180.95,3279.9 187.67,3273.77 L6002.2@182.53,3278.91 ; L6002.2@180.95,3279.9 180.95,3245.17 187.03,3239.09 ; L6002.2@180.95,3279.9 L6002.2@182.53,3278.91 ; L6002.2@181.54,3279.9 183.59,3279.9 188,3275.49 L6002.2@182.53,3278.91 ; L6002.2@181.54,3279.9 L6002.2@182.53,3278.91
PS_LED_ANODE: C6310.1 CON6301.6 R6313.2 | length 97
  Bottom w12: C6310.1@1690.31,4492.09 C6310.1@1691.31,4492.09 ; R6313.2@1691.31,4459.09 C6310.1@1691.31,4492.09 ; CON6301.6@1696.3,4550.11 1696.29,4492.09 C6310.1@1691.31,4492.09
PS_VDD: C6308.1 CON6301.5 R6311.2 | length 101.6
  Bottom w12: R6311.2@1618.31,4495.09 1618.31,4493.85 1620.56,4493.85 1634.8,4508.09 C6308.1@1653.31,4508.09 1666.55,4508.09 1676.61,4518.14 CON6301.5@1676.61,4550.11
PWRAP_INT: R2404.1 U1001.AA2 | length 996.8
  Top w3: U1001.AA2@1298.31,3685.01 U1001.AA2@1297.69,3685.02 1297.69,3654.71 1307.31,3645.09 1307.31,3623.09
  Top w4: 1307.31,3623.09 1307.31,3617.17 1312.97,3611.51 v1(1312.31,3610.85) ; R2404.1@1378.31,2951.09 1377.56,2951.09 1377.56,2951.84 1392.06,2966.34 v1(1398.31,2967.09)
  Inner Layer 2 w4: v3(1287.4,3316.72) 1279.62,3324.5 1279.62,3342.98 1294.47,3357.83 1313.51,3357.83 1337.95,3382.27 1337.95,3585.21 v1(1312.31,3610.85) ; v3(1379.31,3019.09) 1391.71,3006.69 1391.71,2993.39 1394.31,2990.78 1394.31,2969.09 1396.31,2967.09 v1(1398.31,2967.09)
  Inner Layer 5 w4: v2(1222.17,3048.51) 1221.95,3050.83 1217.31,3055.47 1217.31,3211.52 1241.31,3235.52 1241.31,3293.47 1264.57,3316.72 v3(1287.4,3316.72) ; v2(1361.31,3037.09) v3(1379.31,3019.09)
  Bottom w4: v2(1222.17,3048.51) 1223.22,3049.56 1235.69,3037.09 v2(1361.31,3037.09)
PWRAP_SPI0_CK: U1001.Y3 U2001.K6 | length 828.8
  Inner Layer 2 w4: v3(927.95,3195.49) 931.33,3192.11 v4(931.33,3180.2) ; v3(1173.95,3305.83) 1182.34,3314.22 1190.56,3314.22 1200.95,3324.62 1200.95,3331.99 1218.79,3349.83 1247.3,3349.83 1329.95,3432.48 1329.95,3577.46 1309.01,3598.4 1307.79,3598.4 1298.91,3607.28 1298.91,3665.49 1284.7,3679.71 1284.7,3700.76 v4(1281.94,3700.77)
  Inner Layer 4 w4: v3(927.95,3195.49) 953.29,3220.83 1088.95,3220.83 v3(1173.95,3305.83)
  Inner Layer 5 w4: v2@910.93,3195.45 v3(927.95,3195.49)
  other v2: 910.93,3195.4
PWRAP_SPI0_CSN: U1001.Y4 U2001.M6 | length 1318.3
  Inner Layer 2 w3: v3(819.33,3162.05) 822.78,3165.49 885.12,3165.49 v4(899.83,3180.2) ; v4(1281.94,3716.51) 1281.59,3716.16 1292.44,3705.31 1292.44,3681.99 1300.95,3673.49
  Inner Layer 2 w4: v3(1295.86,3338.01) 1306.68,3348.83 1315.83,3348.83 1345.95,3378.95 1345.95,3594.75 1306.95,3633.75 1306.95,3667.49 1300.95,3673.49
  Inner Layer 4 w4: v3(819.33,3162.05) 819.33,3174.07 781.95,3211.45 781.95,3303.36 805.42,3326.83 823.08,3326.83 837.34,3341.09 909.94,3341.09 923.18,3327.85 1067.31,3327.85 1109.04,3369.58 1132.07,3369.58 1194.32,3431.83 1244.87,3431.83 1276.31,3400.39 1276.31,3357.56 v3(1295.86,3338.01)
PWRAP_SPI0_MI: U1001.AB1 U2001.N5 | length 1030.9
  Top w4: v1(1304.9,3566.39) 1313.2,3566.39 1332.67,3585.86 1332.67,3597.17 1332.95,3597.46 1332.95,3620.2 1322.22,3630.94 1321.95,3631.2 1321.95,3652.97 1313.44,3661.48 U1001.AB1@1313.44,3669.27
  Inner Layer 2 w3: 848.31,3201.09 849.31,3201.09 864.31,3186.09 874.22,3186.09 v4(884.09,3195.95)
  Inner Layer 2 w4: v3(803.09,3227.56) 802.45,3227.59 802.28,3224.46 807.48,3224.46 830.86,3201.09 848.31,3201.09 ; v3(1203.95,3416.83) 1204.87,3415.91 1218.78,3429.83 1293.36,3429.83 1305.95,3442.42 1305.95,3527.83 1297.29,3536.49 1297.29,3561.42 1303.58,3567.71 v1(1304.9,3566.39)
  Inner Layer 4 w4: v3(803.09,3227.56) 803.09,3234.22 790.03,3247.28 790.03,3300.12 808.74,3318.83 827.12,3318.83 841.38,3333.09 880.58,3333.09 893.82,3319.85 1071.33,3319.85 1110.17,3358.68 1134.73,3358.68 1184.75,3408.71 1195.83,3408.71 v3(1203.95,3416.83)
PWRAP_SPI0_MO: U1001.AB2 U2001.L6 | length 871.8
  Top w3: U1001.AB2@1313.44,3685.02 1303.95,3675.53 1303.95,3659.49 1314.45,3648.99 1314.45,3627.39 1318.9,3622.94
  Top w4: v1(1305.86,3582.72) 1324.31,3601.17 1324.31,3617.53 1318.9,3622.94
  Inner Layer 2 w4: v4(915.58,3180.2) 934.69,3161.09 v3(940.31,3161.09) ; v3(1184.95,3329.83) 1215.21,3360.09 1246.25,3360.09 1321.95,3435.8 1321.95,3566.62 v1(1305.86,3582.72)
  Inner Layer 4 w4: v3(940.31,3161.09) 912.95,3188.45 912.95,3201.7 941.08,3229.83 1085.89,3229.83 1157.95,3301.89 1157.95,3311.04 1168.74,3321.83 1176.95,3321.83 v3(1184.95,3329.83)
PWRKEY: C6503.1 CON9001.2 R6507.1 U2001.E2 | length 6535.3
  Top w3: U2001.E2@1010.07,3243.19 1010.07,3244.09 1022.31,3256.34 1022.31,3268.21 1042.24,3288.13 1054.65,3288.13 1058.06,3284.72 v1(1058.4,3285.07)
  Inner Layer 2 w4: v1(1058.4,3285.07) 1058.4,3293.38 1057.31,3294.47 1057.31,3311.17 1102.97,3356.83 1138.72,3356.83 1176.72,3394.83 v3(1201.95,3394.83) ; v3(1069.21,2826.07) 1079.97,2836.83 1179.3,2836.83 1213.3,2870.83 1311.96,2870.83 1339.31,2898.18 1339.31,2953.53 1297.75,2995.09 v3(1284.31,2995.09)
  Inner Layer 4 w4: v3(154.45,3172.43) 138.31,3188.57 138.31,3273.5 165.1,3300.29 165.1,3406.69 122.31,3449.47 122.31,3749.16 136.31,3763.16 136.31,3918.09 105.95,3948.45 105.95,3971.37 128.31,3993.73 128.31,4183.44 134.95,4190.08 134.95,4243.51 134.31,4244.15 134.31,4431.5 271.9,4569.09 452.56,4569.09 666.56,4783.09 1325.31,4783.09 1479.31,4937.09 1997.3,4937.09 v3(2039.3,4895.09) ; v3(1201.95,3394.83) 1271.95,3324.83 1271.95,3276.31 1298.07,3250.19 v3(1298.07,3190.26)
  Inner Layer 5 w4: v3(154.45,3172.43) 156.31,3172.43 156.31,3152.86 214.31,3094.86 214.31,2965.09 112.31,2863.09 112.31,2752.19 242.6,2621.9 v2(249.68,2621.9) ; v2(399.33,2625.71) 399.74,2625.71 v2(399.74,2702.55) ; v2(833.92,2857.52) 842.6,2848.85 851.06,2848.85 860.81,2839.09 1005.03,2839.09 1024.03,2820.09 1050.78,2820.09 1056.77,2826.07 v3(1069.21,2826.07) ; v3(1284.31,2995.09) 1298.95,3009.73 1298.95,3068.76 1294.31,3073.4 1294.31,3186.5 v3(1298.07,3190.26) ; v2(2041.31,4910.09) 2040.31,4910.09 v3@2040.31,4895.09 ; v3@2040.31,4895.09 2041.31,4894.09 v3(2039.3,4895.09) v3@2040.31,4895.09
  Bottom w4: v2(249.68,2621.9) 257.84,2630.06 386.68,2630.06 391,2625.74 v2(399.33,2625.71) ; v2(399.33,2625.71) 401.64,2625.74 402.94,2624.43 408.6,2630.09 449.46,2630.09 512.86,2566.7 CON9001.2@559.07,2566.7 ; v2(399.74,2702.55) 399.74,2740.09 503.74,2844.09 820.49,2844.09 v2(833.92,2857.52) ; v2(2041.31,4910.09) 2063.3,4910.09 C6503.1@2065.3,4912.09
RCN: CON6201.2 U1001.N28 | length 567
  Inner Layer 2 w4: v4(1171.71,4094.47) 1171.08,4093.83 1171.08,4072.1 1185.08,4058.1 v3@1186.08,4058.1
  Inner Layer 4 w3: v3(1187.95,4056.49) 1170.31,4074.12 1170.31,4107.09 1155.8,4121.6 1155.8,4267.38 1228.25,4339.83 v3(1232.95,4339.83)
  Inner Layer 5 w4: v3@1232.95,4339.85 1231.97,4340.02 1233.08,4346.61 1251.08,4346.61 v2(1251.08,4345.11)
  Bottom w4: CON6201.2@1131.28,4268.89 1146.31,4268.89 1165.31,4287.89 1165.31,4311.09 1193.31,4339.09 1245.06,4339.09 v2(1251.08,4345.11)
RCN_A: CON6202.5 U1001.R28 | length 1340.2
  Top w4: CON6202.5@1854.69,4923.92 1857.31,4921.3 1857.31,4904.09 1861.43,4899.97 1861.43,4829.22 v1(1857.3,4825.09)
  Inner Layer 2 w4: v4(1203.2,4094.47) 1203.2,4066.36 1214.01,4055.55 1217.95,4056.49 v3(1219.95,4053.49) ; v1(1857.3,4825.09) 1856.8,4825.09 v3@1856.8,4809.49 ; v3@1857.95,4803.49 1858.13,4803.49 1858.13,4818.6 ; v3@1856.8,4809.49 1856.73,4809.01 v3(1856.08,4809.11) 1856.3,4806.09 1856.8,4806.09 v3@1856.8,4809.49 ; v3@1856.8,4809.49 1858.13,4818.6 ; 1858.13,4818.6 1858.51,4821.2 v1@1858.13,4821.25 ; 1858.13,4818.6 v1@1858.13,4821.25 ; v1@1858.13,4821.25 1858.13,4822.09 1858.01,4821.27 v1@1858.13,4821.25
  Inner Layer 4 w3: v3(1219.95,4053.49) 1220.78,4052.67 1236.31,4068.2 1236.31,4080.12 1325.12,4168.93 1325.12,4351.25 1426.95,4453.08 1426.95,4550.68 1535.76,4659.49 1562.95,4659.49 1626.57,4723.11 1757.99,4723.11 1850.3,4815.41 1856.08,4815.41 v3(1856.08,4809.11)
RCP: CON6201.3 U1001.P28 | length 497.5
  Inner Layer 2 w4: v4(1187.46,4094.47) v3@1187.45,4078.49 ; v3(1187.95,4078.49) v3@1187.45,4078.49 ; v3@1187.45,4078.49 1187.08,4078.49 1187.08,4077.49 1187.45,4077.11 v3@1187.45,4078.49
  Inner Layer 4 w3: v3(1187.95,4078.49) 1178.31,4088.13 1178.31,4107.73 1164.8,4121.24 1164.8,4263.66 v3@1223.63,4322.49 ; v3(1230.95,4317.83) 1232.76,4317.16 1232.76,4320.68 v3@1230.95,4322.49
  Inner Layer 5 w4: v3(1230.95,4317.83) 1235.11,4319.46 1240.54,4324.9 1251.85,4324.9 v2(1251.85,4324.82)
  Bottom w4: CON6201.3@1131.28,4253.14 1143.36,4253.14 1174.31,4284.09 1174.31,4307.36 1197.04,4330.09 1246.58,4330.09 v2(1251.85,4324.82)
RCP_A: CON6202.3 U1001.T28 | length 1287.3
  Top w4: CON6202.3@1870.44,4923.92 1870.44,4832.95 v1(1878.3,4825.09)
  Inner Layer 2 w4: v3(1218.95,4075.49) v4(1218.95,4094.47) ; v3(1878.31,4809.09) v1(1878.3,4825.09)
  Inner Layer 4 w3: v3(1218.95,4075.49) 1316.06,4172.6 1316.06,4354.94 1417.95,4456.83 1417.95,4554.4 1532.03,4668.49 1559.15,4668.49 1622.77,4732.11 1754.26,4732.11 1847.77,4825.62 1863.74,4825.62 1879.29,4810.06 v3(1878.31,4809.09) v3@1873.08,4814.32
RDN0: CON6201.11 U1001.P29 | length 271.4
  Inner Layer 2 w4: v4(1187.46,4110.21) 1187.95,4110.71 1187.95,4126.09 v3(1189.3,4126.09)
  Inner Layer 5 w4: v2(1172.08,4135.11) 1180.28,4135.11 v3(1189.3,4126.09)
  Bottom w4: CON6201.11@1131.28,4127.16 1143.31,4127.16 1150.38,4120.09 1197.59,4120.09 1212.77,4135.27 1243.2,4135.27 1250.59,4142.67 1250.59,4153.17 1244.67,4159.09 1198.45,4159.09 1174.47,4135.11 v2(1172.08,4135.11)
RDN0_A: CON6202.17 U1001.R29 | length 1290.5
  Top w4: v1(1756.11,4821.72) 1762.31,4827.93 1762.31,4921.81 CON6202.17@1760.2,4923.92 ; U1001.R29@1202.95,4110.49 1203.2,4110.74 v4(1203.2,4110.21) U1001.R29@1202.95,4110.49
  Inner Layer 2 w3: v4(1203.2,4110.21) 1203.2,4135.23 v3(1219.08,4151.11)
  Inner Layer 2 w4: v3(1749.08,4808.11) 1756.11,4815.13 v1(1756.11,4821.72)
  Inner Layer 4 w3: v3(1219.08,4151.11) 1220.04,4152.06 1220.04,4160.29 1182.58,4197.75 1182.58,4256.83 1219.24,4293.49 1251.48,4293.49 1262.84,4304.85 1262.84,4375.28 1364.23,4476.67 1364.23,4574.23 1476.95,4686.95 1476.95,4779.7 1486.35,4789.11 1513.08,4789.11 1532.08,4770.11 1545.08,4770.11 1564.08,4789.11 1583.4,4789.11 1637.19,4842.9 1695.86,4842.9 1737.64,4801.11 1742.08,4801.11 v3(1749.08,4808.11)
RDN1: CON6201.8 U1001.P31 | length 253.3
  Top w3: U1001.P31@1187.46,4141.71 1188.08,4142.33 1190.34,4144.59 1190.34,4206.37 v1(1204.08,4220.11)
  Inner Layer 2 w4: v1(1204.08,4220.11) 1204.39,4219.8 1214.99,4230.4 1215.3,4230.09 1216.84,4229.85 v3(1216.83,4229.75)
  Inner Layer 5 w4: v3(1216.83,4229.75) 1216.93,4229.85 1216,4230.78 1217.7,4232.49 1225.9,4232.49 1230.36,4228.03 1231.95,4226.83 v2(1231.97,4226.28)
  Bottom w4: CON6201.8@1131.28,4174.4 1148.31,4174.4 1180.43,4206.52 1222.9,4206.52 1231.95,4215.57 1231.95,4226.83 v2(1231.97,4226.28)
RDN1_A: CON6202.29 U1001.U30 | length 1260.8
  Top w4: v1(1662.08,4823.11) 1668.89,4829.91 1668.89,4918.75 CON6202.29@1665.72,4921.92
  Inner Layer 2 w3: v4(1234.7,4125.96) 1234.7,4146.3 1251.94,4163.54 v3(1252.09,4163.54)
  Inner Layer 2 w4: v3(1660.31,4805.09) 1661.2,4805.09 1661.2,4823.11 v1(1662.08,4823.11)
  Inner Layer 4 w3: v3(1252.09,4163.54) 1253.8,4161.83 1266.67,4161.83 1290,4185.17 1290,4365.66 1390.95,4466.61 1390.95,4564.17 1502.95,4676.17 1502.95,4734.2 1511.85,4743.11 1525.81,4743.11 1534.08,4734.83 1534.08,4704.11 1537.08,4701.11 1544.08,4701.11 1547.08,4704.11 1547.08,4732.83 1557.35,4743.11 1574.17,4743.11 1590.17,4759.11 1605.08,4759.11 1610.08,4764.11 1610.08,4775.83 1621.35,4787.11 1634.56,4787.11 1644.08,4777.58 1644.08,4766.11 1651.08,4759.11 1709.08,4759.11 1715.08,4765.11 1715.08,4773.11 1708.08,4780.11 1684.18,4780.11 v3@1659.76,4804.53
RDN2: CON6201.14 U1001.R30 | length 483.8
  Top w3: U1001.R30@1203.2,4125.96 1202.95,4126.21 1202.95,4170.09 1222.95,4190.09 v1(1226.31,4190.09)
  Inner Layer 2 w4: v1(1226.31,4190.09) 1226.31,4192.09 v3(1250.31,4216.09)
  Inner Layer 5 w4: v3(1250.31,4216.09) 1251.31,4215.09 1266.53,4215.09 v2(1266.53,4215.61)
  Bottom w4: CON6201.14@1131.28,4079.91 1157.49,4079.91 1169,4068.4 1169,4047.43 1180.34,4036.09 1228.12,4036.09 1243.31,4051.29 1243.31,4081.27 1296.7,4134.66 1296.7,4168.7 1289.31,4176.09 1279.39,4176.09 1264.95,4190.53 1264.95,4214.04 v2(1266.53,4215.61)
RDN3: CON6201.5 U1001.U31 | length 328.6
  Top w4: U1001.U31@1234.7,4141.71 1234.06,4142.35 1248.95,4157.24 1248.95,4233.49 v1(1250.95,4235.49)
  Inner Layer 2 w4: v1(1250.95,4235.49) 1252.92,4235.49 1252.92,4251.43 v3(1254.89,4251.43)
  Inner Layer 5 w4: v3(1254.89,4251.43) 1254.89,4262.43 1258.89,4266.43 1259.66,4266.43 v2(1269.31,4276.09)
  Bottom w4: CON6201.5@1131.28,4221.64 1148.49,4221.64 1222.18,4295.33 1248.72,4295.33 1250.11,4295.33 v2(1269.31,4276.09)
RDP0: CON6201.12 U1001.N29 | length 321.2
  Inner Layer 2 w4: v4(1171.71,4110.21) 1171.71,4118.5 1173.31,4120.11 1173.31,4133.34 v3(1189.08,4149.11)
  Inner Layer 5 w4: v2(1172.08,4151.11) 1173.7,4149.49 1188.7,4149.49 v3(1189.08,4149.11)
  Bottom w4: CON6201.12@1131.28,4111.41 1146.07,4111.41 1146.39,4111.09 1201.4,4111.09 1216.56,4126.25 1246.97,4126.25 1259.64,4138.91 1259.64,4157.02 1248.57,4168.09 1194.5,4168.09 1177.52,4151.11 v2(1172.08,4151.11)
RDP0_A: CON6202.15 U1001.T29 | length 1302.4
  Top w4: v1(1775.79,4821.72) 1771.31,4826.2 1771.31,4903.09 1775.95,4907.73 CON6202.15@1775.95,4921.92
  Inner Layer 2 w4: v3(1217.62,4127.31) 1218.29,4127.31 1218.29,4110.21 v4(1218.95,4110.21) ; v3(1771.08,4806.11) 1771.29,4805.9 1775.79,4810.41 v1(1775.79,4821.72)
  Inner Layer 4 w3: v3(1217.62,4127.31) 1218.08,4128.11 1233.58,4143.61 1233.58,4159.97 1191.58,4201.97 1191.58,4252.97 1222.95,4284.34 1255.06,4284.34 1271.84,4301.12 1271.84,4371.55 1373.23,4472.94 1373.23,4570.5 1485.95,4683.22 1485.95,4775.91 1490.15,4780.11 1509.35,4780.11 1528.63,4760.83 1548.88,4760.83 1567.99,4779.94 1580.2,4779.94 1580.31,4779.83 1586.86,4779.83 1640.86,4833.83 1692.17,4833.83 1734.39,4791.61 1756.58,4791.61 v3(1771.08,4806.11)
RDP1: CON6201.9 U1001.P30 | length 235.3
  Top w3: U1001.P30@1187.46,4125.96 1196.92,4135.42 1196.92,4189.03 v1(1202.69,4194.81)
  Inner Layer 2 w4: v1(1202.69,4194.81) 1203.5,4194 1218.14,4208.64 v3(1218.95,4207.83)
  Inner Layer 5 w4: v3(1218.95,4207.83) 1217.61,4206.49 1230.13,4193.98 v2(1228.79,4192.64)
  Bottom w4: CON6201.9@1131.28,4158.65 1145.32,4158.65 1184.18,4197.52 1223.85,4197.52 1228.72,4192.65 v2(1228.79,4192.64)
RDP1_A: CON6202.27 U1001.V30 | length 1254.4
  Top w4: CON6202.27@1681.46,4923.92 1677.89,4920.35 1677.89,4827.55 v1(1681.95,4823.49)
  Inner Layer 2 w4: v4(1250.45,4125.96) 1250.08,4126.33 v3(1250.08,4141.11) ; v1(1681.95,4823.49) 1682.08,4823.36 1682.08,4806.11 v3(1683.08,4805.11) ; v3(1250.08,4141.11) 1252.09,4141.17 1252.12,4141.76 1250.94,4141.85 1250.82,4141.85 v3(1250.08,4141.11)
  Inner Layer 4 w3: v3(1250.08,4141.11) 1250.08,4142.49 1260.58,4142.49 1299,4180.91 1299,4361.93 1399.95,4462.88 1399.95,4560.44 1511.95,4672.44 1511.95,4730.48 1515.58,4734.11 1522.08,4734.11 1525.08,4731.11 1525.08,4700.38 1534.35,4691.11 1546.81,4691.11 1556.08,4700.38 1556.08,4729.11 1561.08,4734.11 1577.9,4734.11 1586.61,4742.82 1593.9,4750.11 1608.81,4750.11 1619.2,4760.5 1619.2,4772.23 1625.08,4778.11 1630.83,4778.11 1635.08,4773.86 1635.08,4762.38 1647.35,4750.11 1712.81,4750.11 1724.09,4761.39 1724.09,4777.1 1712.08,4789.11 1687.91,4789.11 1682.28,4794.74 1682.28,4804.3 v3(1683.08,4805.11)
RDP2: CON6201.15 U1001.T30 | length 478.6
  Top w3: U1001.T30@1218.95,4125.96 1208.95,4135.96 1208.95,4164.09 1218.95,4174.09 v1(1225.31,4174.09)
  Inner Layer 2 w4: v1(1225.31,4174.09) 1226.3,4173.1 1235.6,4182.4 1238.52,4182.4 v3(1249.95,4193.83)
  Inner Layer 5 w4: v3(1249.95,4193.83) 1251.89,4195.77 1275.35,4195.77 v2(1279.17,4199.59)
  Bottom w4: CON6201.15@1131.28,4064.16 1140.31,4064.16 1144.24,4068.09 1155.31,4068.09 1160,4063.4 1160,4043.7 1176.62,4027.09 1231.84,4027.09 1252.31,4047.56 1252.31,4077.5 1305.72,4130.9 1305.72,4172.42 1293.05,4185.09 1283.15,4185.09 1279.17,4189.07 v2(1279.17,4199.59)
RDP3: CON6201.6 U1001.T31 | length 317.1
  Top w4: U1001.T31@1218.95,4141.71 1218.06,4142.59 1239.95,4164.48 1239.95,4227.4 1234.95,4232.4 v1(1234.95,4239.49)
  Inner Layer 2 w4: v3(1232.95,4255.49) 1233.95,4255.49 1233.95,4239.49 v1(1234.95,4239.49)
  Inner Layer 5 w4: v3(1232.95,4255.49) 1231.85,4256.59 1249.81,4274.55 v2(1248.71,4275.64)
  Bottom w4: CON6201.6@1131.28,4205.9 1131.28,4208.1 1147.7,4208.1 1225.91,4286.31 1246.38,4286.31 1248.72,4283.97 v2(1248.71,4275.64)
REFP: C1104.1 U1001.AL10 | length 46.9
  Top w4: U1001.AL10@1455.17,3811 1463.8,3811 1477.71,3797.09 C1104.1@1496.3,3797.09
RF_ANT_DRX_SWITCH: C3499.2 L3499.1 U3402.13 | length 68.9
  Bottom w5: U3402.13@2183.31,4013.15 2197.69,4013.15 2217.25,3993.59 L3499.1@2219.15,3993.59 C3499.2@2244.15,3993.59
RF_ANT_TRX_1: C3801.1 CON3802.1 L3801.1 | length 55.2
  Bottom w5: C3801.1@2155.95,4309.83 L3801.1@2155.95,4331.83 2155.95,4355.16 CON3802.1@2162.95,4362.16
RF_ANT_TRX_2: C3801.2 DIPX3801.5 L3802.1 | length 142.8
  Top w5: v1(2159.06,4406.09) 2159.33,4406.09 DIPX3801.5@2160.33,4405.09
  Inner Layer 2 w4: v3(2158.74,4391.01) 2159.06,4389.33 v1(2159.06,4406.09)
  Inner Layer 4 w4: v3(2158.74,4391.01) 2158.74,4354.75 v3(2188.66,4324.83)
  Inner Layer 5 w4: v2(2176.95,4310.83) 2176.38,4311.4 2189.23,4324.26 v3(2188.66,4324.83)
  Bottom w5: v2(2176.95,4310.83) C3801.2@2175.95,4309.83 2175.95,4329.83 L3802.1@2177.95,4331.83
RF_ANT_TRX_3: DIPX3801.1 L3803.1 R3801.1 | length 57.1
  Top w5: R3801.1@2070.33,4376.09 L3803.1@2094.33,4376.09 2121.19,4376.09 DIPX3801.1@2125.6,4380.5
RF_ANT_TRX_4: L3804.1 LPF3801.4 R3801.2 R3802.1 | length 69.7
  Top w5: LPF3801.4@2044.05,4431.4 2070.33,4431.4 ; R3801.2@2070.33,4396.09 L3804.1@2070.33,4417.09 2070.33,4431.4 ; R3802.1@2071.33,4439.09 2070.33,4438.09 2070.33,4431.4
RF_ANT_TRX_5: L3805.1 LPF3801.6 R3802.2 R3804.1 | length 80
  Top w5: LPF3801.6@2044.05,4470.78 2059.64,4470.77 R3802.2@2071.33,4459.09 ; R3802.2@2070.01,4457.77 R3802.2@2071.33,4459.09 ; R3804.1@2092.33,4484.09 L3805.1@2092.33,4459.09 R3802.2@2071.33,4459.09
RF_ANT_TRX_ASM: L3806.1 R3804.2 U3801.13 | length 82.8
  Top w5: 2072.31,4495.09 L3806.1@2072.31,4506.09 2093.3,4506.09 2110.3,4523.09 U3801.13@2110.3,4538.85 ; R3804.2@2072.33,4484.09 2072.33,4495.08
RF_ANT_TRX_CARKIT: C3310.1 CON3301.1 | length 304.7
  Top w5: C3310.1@2361.65,3703.59 2361.72,3703.65 v1(2363.52,3703.65)
  Inner Layer 2 w3: v1@2363.52,3703.62 v3(2379.08,3703.58)
  Inner Layer 5 w3: v3(2379.08,3703.58) v2(2395.08,3703.58)
  Bottom w5: v2(2395.08,3703.58) 2439.31,3659.35 CON3301.1@2439.31,3450.76
RF_ANT_TRX_TXM: C3310.2 L3322.1 U3307.22 | length 73
  Top w5: U3307.22@2307.35,3653.03 2307.35,3660.59 cw(c2321.14,3660.59) 2311.39,3670.35 2316.84,3675.8 cw(c2335.65,3656.98) 2335.65,3683.59 L3322.1@2336.65,3683.59 C3310.2@2361.65,3683.59
RF_B1_DRX_MT6169_RFIN2_HB3: C3405.2 L3403.1 U3101.E2 | length 101.6
  Top w3: U3101.E2@1958.15,3993.08 1964.82,3999.75 ccw(c1957.98,4006.59) 1967.65,4006.59 1967.65,4013.59 ccw(c1960.41,4013.59) 1965.54,4018.71 1964.65,4019.59
  Top w4: C3405.2@1925.65,4070.59 1926.07,4070.17 cw(c1915,4059.11) 1930.65,4059.11 L3403.1@1930.65,4045.59 1932.65,4043.59 1932.65,4043.1 1941.41,4034.35 ccw(c1945.65,4038.59) 1945.65,4032.59 1946.65,4032.59 cw(c1946.65,4020.52) 1955.19,4029.05 1964.65,4019.59
RF_B1_DRX_MT6169_RFIP2_HB3: C3401.2 L3403.2 U3101.D2 | length 87.3
  Top w3: 1969.65,4027.42 1970.66,4026.42 cw(c1962.83,4018.59) 1973.9,4018.59 U3101.D2@1973.9,3993.08
  Top w4: L3403.2@1950.65,4045.59 L3403.2@1950.65,4046 ; C3401.2@1950.65,4070.59 L3403.2@1950.65,4046 ; 1969.65,4027.42 1951.07,4046 L3403.2@1950.65,4046
RF_B1_DRX_SAW: L3421.1 L3443.2 U3403.1 | length 56.3
  Bottom w5: L3443.2@1869.15,4013.59 L3421.1@1869.15,4038.59 U3403.1@1869.15,4069.89
RF_B1_DRX_SAW_RFIN2_HB1: C3405.1 L3401.1 U3403.3 | length 159.7
  Top w4: C3405.1@1925.65,4090.59 1926.13,4091.06 ccw(c1915.2,4101.99) 1930.65,4101.99 L3401.1@1930.65,4115.59
  Inner Layer 2 w4: v3(1882.03,4159.55) 1898.47,4143.11 1903.57,4143.11 v1(1930.91,4115.78)
  Inner Layer 5 w4: v2(1861.31,4119.98) 1872.32,4130.99 1872.32,4135.91 1873.86,4137.45 1873.86,4137.52 1882.03,4145.69 v3(1882.03,4159.55)
  Bottom w4: U3403.3@1857.83,4105.32 1861.31,4105.34 v2(1861.31,4119.98)
RF_B1_DRX_SAW_RFIP2_HB1: C3401.1 L3401.2 U3403.4 | length 159
  Top w4: C3401.1@1950.65,4090.59 L3401.2@1950.65,4115.59 v1(1951.04,4115.98)
  Inner Layer 2 w4: v3(1906.05,4158.33) 1906.05,4152.01 1930.07,4128 1939.01,4128 v1(1951.04,4115.98)
  Inner Layer 5 w4: v2(1881.82,4119.28) 1881.16,4118.62 1880.32,4118.25 1880.32,4132.6 v3(1906.05,4158.33)
  Bottom w4: U3403.4@1880.47,4105.32 1881.98,4106.83 1881.98,4119.12 v2(1881.82,4119.28)
RF_B1_DRX_SWITCH: L3443.1 U3402.1 | length 462.5
  Bottom w5: L3443.1@1869.15,3993.59 1880.87,3981.88 1880.87,3954.6 1892.91,3942.55 1892.91,3909.03 1932.07,3869.88 2115.44,3869.88 2172.39,3926.82 U3402.1@2172.39,3975.65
